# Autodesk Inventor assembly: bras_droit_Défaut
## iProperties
Shininess: 64.0
Length Units: 11269
Angle Units: 11279
Time Units: 11290
Mass Units: 11283
Length Display Precision: 3
Angle Display Precision: 2
Compacted: True
Created: 2006-01
Part Number: bras_droit_Défaut
Document SubType Name: Assembly
Designer: riri
Density: 0.0
Volumn: 0.0
Area: 0.0
PropertySet Name: Model Information
Control State: 0
Master: False
Checked Out: False
Author: riri
